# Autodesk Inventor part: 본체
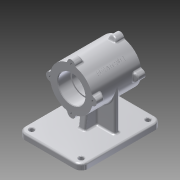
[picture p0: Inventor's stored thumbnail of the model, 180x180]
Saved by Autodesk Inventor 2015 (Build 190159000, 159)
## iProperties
Created: 2015-12
Part Number: 본체
Material: 알루미늄 6061
Document SubType Name: Modeling
Designer: Administrator
Density: 2.7 g/cm^3
Appearance: 알루미늄 - 평지
Mass: 1161.08 g
Surface Area: 815.069 cm^2
Volume: 430.029 cm^3
Author: Administrator
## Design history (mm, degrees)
sketch "스케치1"
  geometry: L1 (-55, 60)-(55, 60); L2 (55, 60)-(55, -80); L3 (55, -80)-(-55, -80); L4 (-55, -80)-(-55, 60); 1 further point
  constraints: 8 end point, 2 parallel, 1 horizontal, 1 perpendicular
  dimensions: "d0" = 110 distance between parallel lines of L2 L4; "d1" = 140 distance between parallel lines of L3 L1; "d2" = 80 distance from line of L3 point (0, 0); "d3" = 55 distance from line of L4 point (0, 0)
extrude "돌출1" new body sketch "스케치1" distance "d4" = 10; taper "d5" = 0 deg
fillet "모깎기1" dims "d6" = 12
hole "구멍1" diameter "d10" = 8; stored, may be unused: countersink angle "d14" = 90 deg, drill point angle "d16" = 118 deg; dims "d8" = 10, "d9" = 10, "d11" = 6, "d12" = 4, "d13" = 2, "d15" = 8
hole "구멍2" diameter "d19" = 8; stored, may be unused: countersink angle "d23" = 90 deg, drill point angle "d25" = 118 deg; dims "d17" = 10, "d18" = 10, "d20" = 6, "d21" = 4, "d22" = 2, "d24" = 8
hole "구멍3" diameter "d28" = 8; stored, may be unused: countersink angle "d32" = 90 deg, drill point angle "d34" = 118 deg; dims "d26" = 10, "d27" = 10, "d29" = 6, "d30" = 4, "d31" = 2, "d33" = 8
hole "구멍4" diameter "d37" = 8; stored, may be unused: countersink angle "d41" = 90 deg, drill point angle "d43" = 118 deg; dims "d35" = 10, "d36" = 10, "d38" = 6, "d39" = 4, "d40" = 2, "d42" = 8
fillet "모깎기2" dims "d7" = 3
node "작업 평면1"
sketch "스케치2"
  geometry: L1 (0, 0)-(86, 0) reference; C1 r 37 at (43, 80); 1 further point
  constraints: 1 centre point
  dimensions: "d45" = 74 diameter of C1; "d46" = 80 distance from line of L1 C1.centre
extrude "돌출2" join sketch "스케치2" stored distance "d47" = 85; taper "d48" = 0 deg
sketch "스케치3"
  geometry: L1 (55, -73)-(55, -80) reference; L2 (55, -80)-(-55, -80) reference; L3 (-55, -80)-(-55, -73) reference; L4 (-52, -70)-(52, -70) reference; A1 r 3 centre (52, -73) between (55, -73) and (52, -70) reference; A2 r 3 centre (-52, -73) between (-52, -70) and (-55, -73) reference; A3 r 7 centre (0, 37) between (6.969, 36.338) and (-6.969, 36.338); A4 r 7 centre (-37, 0) between (-36.338, 6.969) and (-36.338, -6.969); A5 r 7 centre (0, -37) between (-6.969, -36.338) and (6.969, -36.338); A6 r 7 centre (37, 0) between (36.338, -6.969) and (36.338, 6.969); 2 further points
  constraints: 8 point on circle, 4 centre point, 10 other
  dimensions: "d49" = 14 diameter of A3
extrude "돌출3" join sketch "스케치3" distance "d53" = 15; taper "d54" = 0 deg
sketch "스케치4"
  geometry: L1 (-42.5, 124)-(-27.5, 124) reference; L2 (-27.5, 124)-(-27.5, 117) reference; L3 (-27.5, 117)-(42.5, 117) reference; L4 (42.5, 117)-(42.5, 43) reference; L5 (42.5, 43)-(-27.5, 43) reference; L6 (-27.5, 43)-(-27.5, 36) reference; L7 (-27.5, 36)-(-42.5, 36) reference; L8 (-42.5, 36)-(-42.5, 124) reference; L9 (60, 7)-(60, 0) reference; L10 (60, 0)-(-80, 0) reference; L11 (-80, 0)-(-80, 7) reference; L12 (-77, 10)-(57, 10) reference; L13 (-27.5, 117)-(-30.048, 124); L14 (-42.5, 80)-(42.5, 80); A1 r 3 centre (57, 7) between (60, 7) and (57, 10) reference; A2 r 3 centre (-77, 7) between (-77, 10) and (-80, 7) reference; 1 further point
  constraints: 4 end point, 2 midpoint, 1 point on line
  dimensions: "d55" = 110 deg angle of L3 L13; "d56" = 74 diameter of L3 L14 (derived)
revolve "회전1" sketch "스케치4" stored, may be unused: angle "d57" = 90 deg
hole "구멍5" diameter "d60" = 3.242; stored, may be unused: countersink angle "d64" = 90 deg, drill point angle "d66" = 118 deg; dims "d58" = 10, "d59" = 10, "d61" = 9, "d62" = 4, "d63" = 2, "d65" = 11
hole "구멍6" diameter "d69" = 3.242; stored, may be unused: countersink angle "d73" = 90 deg, drill point angle "d75" = 118 deg; dims "d67" = 10, "d68" = 10, "d70" = 9, "d71" = 4, "d72" = 2, "d74" = 11
hole "구멍7" diameter "d78" = 3.242; stored, may be unused: countersink angle "d82" = 90 deg, drill point angle "d84" = 118 deg; dims "d76" = 10, "d77" = 10, "d79" = 9, "d80" = 4, "d81" = 2, "d83" = 11
hole "구멍8" diameter "d87" = 3.242; stored, may be unused: countersink angle "d91" = 90 deg, drill point angle "d93" = 118 deg; dims "d85" = 10, "d86" = 10, "d88" = 9, "d89" = 4, "d90" = 2, "d92" = 11
hole "구멍9" diameter "d96" = 42; stored, may be unused: countersink angle "d100" = 90 deg, drill point angle "d102" = 0 deg; dims "d94" = 10, "d95" = 10, "d97" = 9, "d98" = 47, "d99" = 22, "d101" = 41
hole "구멍10" diameter "d105" = 47; stored, may be unused: countersink angle "d109" = 90 deg, drill point angle "d111" = 0 deg; dims "d103" = 10, "d104" = 10, "d106" = 9, "d107" = 4, "d108" = 2, "d110" = 22
fillet "모깎기3" dims "d112" = 0.3
chamfer "모따기1" distance "d113" = 1; stored, may be unused: second distance "d114" = 2, angle "d115" = 45 deg
chamfer "모따기2" distance "d116" = 1; stored, may be unused: second distance "d117" = 2, angle "d118" = 45 deg
sketch "스케치5"
  geometry: L1 (60, 7)-(60, 0) reference; L2 (60, 0)-(-80, 0) reference; L3 (-80, 0)-(-80, 7) reference; L4 (-77, 10)-(57, 10) reference; L5 (-27.5, 43)-(-30.048, 36) reference; L6 (-30.048, 36)-(-42.5, 36) reference; L7 (-42.5, 36)-(-42.5, 41.379) reference; L8 (-42.5, 41.379)-(-31.5, 41.379) reference; L9 (-31.5, 41.379)-(-30.526, 43) reference; L10 (-30.526, 43)-(-31.5, 44.621) reference; L11 (-31.5, 44.621)-(-42.5, 44.621) reference; L12 (-42.5, 44.621)-(-42.5, 55.5) reference; L13 (-42.5, 55.5)-(-41.5, 56.5) reference; L14 (-41.5, 56.5)-(-20.8, 56.5) reference; L15 (-20.5, 56.8)-(-20.5, 59) reference; L16 (-20.5, 59)-(20.5, 59) reference; L17 (20.5, 59)-(20.5, 56.8) reference; L18 (20.8, 56.5)-(41.5, 56.5) reference; L19 (41.5, 56.5)-(42.5, 55.5) reference; L20 (42.5, 55.5)-(42.5, 44.621) reference; L21 (42.5, 44.621)-(31.5, 44.621) reference; L22 (31.5, 44.621)-(30.526, 43) reference; L23 (30.526, 43)-(31.5, 41.379) reference; L24 (31.5, 41.379)-(42.5, 41.379) reference; L25 (42.5, 41.379)-(42.5, 36) reference; L26 (42.5, 36)-(30.048, 36) reference; L27 (30.048, 36)-(27.5, 43) reference; L28 (27.5, 43)-(-27.5, 43) reference; L29 (-30.048, 124)-(-27.5, 117) reference; L30 (-27.5, 117)-(27.5, 117) reference; L31 (27.5, 117)-(30.048, 124) reference; L32 (30.048, 124)-(42.5, 124) reference; L33 (42.5, 124)-(42.5, 118.621) reference; L34 (42.5, 118.621)-(31.5, 118.621) reference; L35 (31.5, 118.621)-(30.526, 117) reference; L36 (30.526, 117)-(31.5, 115.379) reference; L37 (31.5, 115.379)-(42.5, 115.379) reference; L38 (42.5, 115.379)-(42.5, 104.5) reference; L39 (42.5, 104.5)-(41.5, 103.5) reference; L40 (41.5, 103.5)-(20.8, 103.5) reference; L41 (20.5, 103.2)-(20.5, 101) reference; L42 (20.5, 101)-(-20.5, 101) reference; L43 (-20.5, 101)-(-20.5, 103.2) reference; L44 (-20.8, 103.5)-(-41.5, 103.5) reference; L45 (-41.5, 103.5)-(-42.5, 104.5) reference; L46 (-42.5, 104.5)-(-42.5, 115.379) reference; L47 (-42.5, 115.379)-(-31.5, 115.379) reference; L48 (-31.5, 115.379)-(-30.526, 117) reference; L49 (-30.526, 117)-(-31.5, 118.621) reference; L50 (-31.5, 118.621)-(-42.5, 118.621) reference; L51 (-42.5, 118.621)-(-42.5, 124) reference; L52 (-42.5, 124)-(-30.048, 124) reference; L53 (20.334, 48)-(25, 10); L54 (-20.334, 48)-(-25, 10); L55 (-20.334, 48)-(20.334, 48); A1 r 3 centre (57, 7) between (60, 7) and (57, 10) reference; A2 r 3 centre (-77, 7) between (-77, 10) and (-80, 7) reference; A3 r 0.3 centre (-20.8, 56.8) between (-20.8, 56.5) and (-20.5, 56.8) reference; A4 r 0.3 centre (20.8, 56.8) between (20.5, 56.8) and (20.8, 56.5) reference; A5 r 0.3 centre (20.8, 103.2) between (20.8, 103.5) and (20.5, 103.2) reference; A6 r 0.3 centre (-20.8, 103.2) between (-20.5, 103.2) and (-20.8, 103.5) reference; 1 further point
  constraints: 6 end point, 2 point on line, 1 horizontal
  dimensions: "d119" = 97 deg angle of L4 L53; "d120" = 97 deg angle of L4 L54; "d121" = 25 horizontal distance of L53.end point (0, 0); "d122" = 50 distance of L53.end L54.end (= 2 x d121); "d123" = 38 distance between parallel lines of L4 L55; "d124" = 42.5 distance from line of L20 point (0, 0) (derived)
feature "리브1" sketch "스케치5" dims "d125" = 1, "d126" = 12, "d127" = 0, "d128" = 0, "d129" = 1, "d130" = 1
sketch "리브스케치공유"
  geometry: L1 (-52, 10)-(-6, 10) reference; L2 (-6, 10)-(-6, 43.49) reference; L3 (6, 43.49)-(6, 10) reference; L4 (6, 10)-(52, 10) reference; L5 (55, 7)-(55, 0) reference; L6 (55, 0)-(-55, 0) reference; L7 (-55, 0)-(-55, 7) reference; L8 (-37, 80)-(-37, 10); L9 (37, 80)-(37, 10); C1 r 21 at (0, 80) reference; A1 r 3 centre (-52, 7) between (-52, 10) and (-55, 7) reference; A2 r 37 centre (0, 80) between (6, 43.49) and (-6, 43.49) reference; A3 r 3 centre (52, 7) between (55, 7) and (52, 10) reference; 1 further point
  constraints: 4 end point, 2 point on circle, 2 point on line, 2 tangent, 1 perpendicular, 1 vertical
  node "절단 모서리 투영4"
feature "리브2" dims "d131" = 1, "d132" = 8, "d133" = 0, "d134" = 0, "d135" = 1, "d136" = 1
feature "리브3" dims "d137" = 1, "d138" = 8, "d139" = 0, "d140" = 0, "d141" = 1, "d142" = 1
fillet "모깎기4" dims "d143" = 3
fillet "모깎기5" dims "d144" = 3
fillet "모깎기6" dims "d145" = 3
fillet "모깎기7" dims "d146" = 3
sketch "엠보싱기준"
  geometry: L1 (0, 80)-(-26.163, 106.163); L2 (0, 80)-(37, 80); 1 further point
  constraints: 4 end point, 1 equal length, 1 horizontal
  dimensions: "d147" = 37 distance of L1.start L1.end; "d148" = 135 deg angle of L2 L1
node "엠보싱작업평면"
sketch "스케치8"
  geometry: L1 (42.5, 37)-(-42.5, 37) reference; L2 (-42.5, 18.921)-(-42.5, -18.921) reference; 3 further points
  constraints: 1 coincident, 1 other
  dimensions: "d149" = 42.5 distance from line of point (0, 0) L2 (derived)
feature "엠보싱1" sketch "스케치8" dims "d10" = 8, "d12" = 4, "d13" = 2, "d15" = 8, "d150" = 0.5, "d151" = 0
chamfer "모따기3" distance "d152" = 1; stored, may be unused: second distance "d153" = 2, angle "d154" = 45 deg
node "솔리드1"
mirror "대칭1"
node "절단 모서리 투영1"
node "절단 모서리 투영2"
node "절단 모서리 투영3"
